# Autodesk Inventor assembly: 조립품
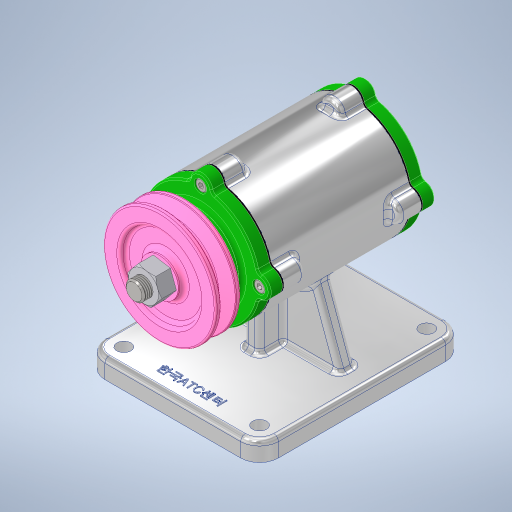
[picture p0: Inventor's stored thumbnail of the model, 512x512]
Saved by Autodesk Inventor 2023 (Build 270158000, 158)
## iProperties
Created: 2023-08
Part Number: 조립품
Document SubType Name: Assembly
Designer: asung
Author: asung
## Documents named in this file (12)
- C:\Users\asung\Desktop\730808V1001\조립품.iam
- C:\Users\asung\Desktop\730808V1001\본체.ipt
- C:\Users\asung\Desktop\730808V1001\개스킷.ipt
- C:\Users\asung\Desktop\730808V1001\뒤커버.ipt
- C:\Users\asung\Desktop\730808V1001\앞커버.ipt
- C:\Users\asung\Desktop\730808V1001\베어링 6204.ipt
- C:\Users\asung\Desktop\730808V1001\축.ipt
- C:\Users\asung\Desktop\730808V1001\오일 실.ipt
- C:\Users\asung\Desktop\730808V1001\키 4 x 4.ipt
- C:\Users\asung\Desktop\730808V1001\V-벨트풀리.ipt
- C:\Users\asung\Desktop\730808V1001\너트 M12 x 1.25.ipt
- C:\Users\asung\Desktop\730808V1001\볼트 M4 x 12.ipt
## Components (8 placed, 6 different names)
1. 개스킷:1
2. 개스킷:2
3. KS B 2023 6204 - 20 x 47 x 14:1
4. KS B 2023 6204 - 20 x 47 x 14:2
5. KS B 2804 D D - 20 32 8:1
6. KS B 1311 (I) 4 x 4 x 12:1
7. V-벨트풀리:1
8. KS B 1012 클래스 1 일반 - 미터 M12x1.25:1
